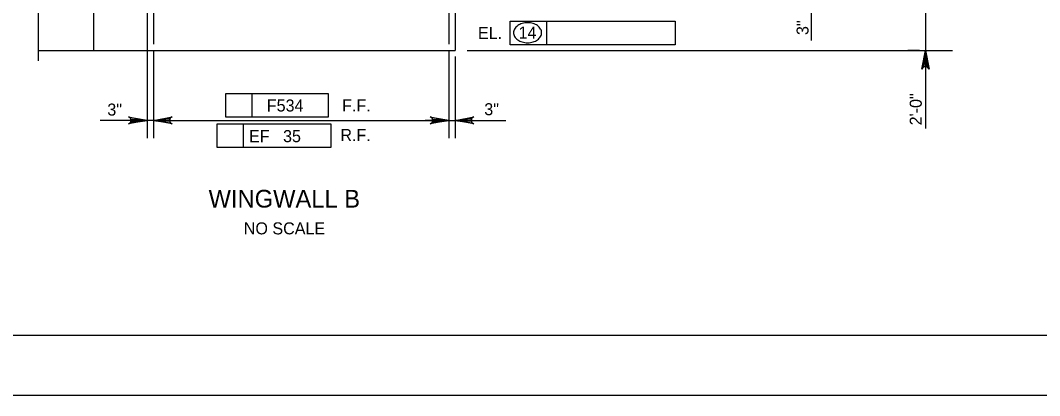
# Model space of a CAD drawing. Extents: x 638255 to 640306, y 296059 to 298435.
# Drawn here: x 638795.2 to 639049.4, y 296059.5 to 296153 of the extents above; entities that cross this region are included whole.
import ezdxf

# ---------------------------------------------------------------- set-up
doc = ezdxf.new("R2010")
doc.units = 0
for name, color, linetype in [('2', 7, 'Continuous'), ('Level 10', 7, 'Continuous'), ('Level 3', 7, 'Continuous'), ('Level 4', 7, 'Continuous'), ('Level 6', 7, 'Continuous'), ('PLT-BNDY', 7, 'Continuous')]:
    doc.layers.add(name, color=color, linetype=linetype)

msp = doc.modelspace()

# ---------------------------------------------------------------- linework, layer by layer
at = {"layer": '2'}
msp.add_line((639261.46, 296074.46), (638475.46, 296074.46), dxfattribs=at)
at = {"layer": 'Level 10'}
for p, q in [((638903.63, 296219.78), (638903.63, 296145.49)), ((638813.44, 296157.77), (638813.44, 296145.49)), ((638799.67, 296145.49), (638903.63, 296145.49))]:
    msp.add_line(p, q, dxfattribs=at)
at = {"layer": 'Level 3'}
msp.add_line((638799.67, 296173.39), (638799.67, 296142.87), dxfattribs=at)
at = {"layer": 'Level 4'}
for p, q in [((638992.48, 296147.95), (638992.48, 296213.97)), ((638826.89, 296156.23), (638826.89, 296123.63)), ((639020.95, 296157.77), (639020.95, 296145.49)), ((638917.35, 296152.73), (638958.48, 296152.73)), ((638917.35, 296146.83), (638917.35, 296152.73)), ((638926.5, 296146.83), (638926.5, 296152.73)), ((638958.48, 296152.73), (638958.48, 296146.83)), ((638828.42, 296145.49), (638828.42, 296123.63)), ((638902.1, 296145.49), (638902.1, 296123.63)), ((638906.62, 296145.49), (638996.24, 296145.49)), ((638958.48, 296146.83), (638917.35, 296146.83)), ((638996.24, 296145.49), (639027.68, 296145.49)), ((639019.48, 296145.49), (639016.53, 296145.49)), ((638903.63, 296143.95), (638903.63, 296123.63)), ((639020.95, 296142.54), (639020.95, 296126.02)), ((638846.5, 296134.75), (638871.98, 296134.75)), ((638846.5, 296128.86), (638846.5, 296134.75)), ((638853.07, 296128.86), (638853.07, 296134.75)), ((638871.98, 296134.75), (638871.98, 296128.86)), ((638820.99, 296128.05), (638815.16, 296128.05)), ((638823.94, 296128.05), (638820.99, 296128.05)), ((638828.42, 296128.05), (638826.89, 296128.05)), ((638831.37, 296128.05), (638899.15, 296128.05)), ((638831.37, 296128.05), (638834.31, 296128.05)), ((638871.98, 296128.86), (638846.5, 296128.86)), ((638899.15, 296128.05), (638896.2, 296128.05)), ((638902.1, 296128.05), (638903.63, 296128.05)), ((638906.58, 296128.05), (638909.53, 296128.05)), ((638909.53, 296128.05), (638916.29, 296128.05)), ((638844.33, 296127.2), (638872.69, 296127.2)), ((638844.33, 296121.31), (638844.33, 296127.2)), ((638850.91, 296121.31), (638850.91, 296127.2)), ((638872.69, 296127.2), (638872.69, 296121.31)), ((638872.69, 296121.31), (638844.33, 296121.31))]:
    msp.add_line(p, q, dxfattribs=at)
for points in [[(639020.95, 296145.49), (639021.82, 296140.84), (639021.57, 296141.2), (639021.26, 296141.38), (639020.95, 296141.43), (639020.63, 296141.38), (639020.32, 296141.2), (639020.07, 296140.84), (639020.95, 296145.49), (639020.32, 296141.2), (639020.63, 296141.38), (639020.95, 296145.49), (639020.95, 296141.43), (639021.26, 296141.38), (639020.95, 296145.49), (639021.57, 296141.2)], [(638826.89, 296128.05), (638822.23, 296127.18), (638822.59, 296127.42), (638822.78, 296127.74), (638822.83, 296128.05), (638822.78, 296128.36), (638822.59, 296128.67), (638822.23, 296128.92), (638826.89, 296128.05), (638822.59, 296128.67), (638822.78, 296128.36), (638826.89, 296128.05), (638822.83, 296128.05), (638822.78, 296127.74), (638826.89, 296128.05), (638822.59, 296127.42)], [(638828.42, 296128.05), (638833.07, 296128.92), (638832.71, 296128.67), (638832.53, 296128.36), (638832.47, 296128.05), (638832.53, 296127.74), (638832.71, 296127.42), (638833.07, 296127.18), (638828.42, 296128.05), (638832.71, 296127.42), (638832.53, 296127.74), (638828.42, 296128.05), (638832.47, 296128.05), (638832.53, 296128.36), (638828.42, 296128.05), (638832.71, 296128.67)], [(638902.1, 296128.05), (638897.45, 296127.18), (638897.8, 296127.42), (638897.99, 296127.74), (638898.04, 296128.05), (638897.99, 296128.36), (638897.8, 296128.67), (638897.45, 296128.92), (638902.1, 296128.05), (638897.8, 296128.67), (638897.99, 296128.36), (638902.1, 296128.05), (638898.04, 296128.05), (638897.99, 296127.74), (638902.1, 296128.05), (638897.8, 296127.42)], [(638903.63, 296128.05), (638908.28, 296128.92), (638907.93, 296128.67), (638907.74, 296128.36), (638907.69, 296128.05), (638907.74, 296127.74), (638907.93, 296127.42), (638908.28, 296127.18), (638903.63, 296128.05), (638907.93, 296127.42), (638907.74, 296127.74), (638903.63, 296128.05), (638907.69, 296128.05), (638907.74, 296128.36), (638903.63, 296128.05), (638907.93, 296128.67)]]:
    msp.add_lwpolyline(points, dxfattribs=at)
for points in [[(639020.46, 296142.54), (639021.44, 296142.54), (639020.95, 296145.49)], [(638823.94, 296128.54), (638823.94, 296127.56), (638826.89, 296128.05)], [(638831.37, 296128.54), (638831.37, 296127.56), (638828.42, 296128.05)], [(638899.15, 296128.54), (638899.15, 296127.56), (638902.1, 296128.05)], [(638906.58, 296128.54), (638906.58, 296127.56), (638903.63, 296128.05)]]:
    msp.add_lwpolyline(points, close=True, dxfattribs=at)
for centre, radius, start, end in [((638920.05, 296149.89), 1.82, 149.9767, 180), ((638920.85, 296149.42), 2.75, 125.6316, 149.9767), ((638921.38, 296148.69), 3.65, 106.5358, 125.6316), ((638921.72, 296147.53), 4.86, 90, 106.5358), ((638921.72, 296147.53), 4.86, 73.4642, 90), ((638922.06, 296148.69), 3.65, 54.3684, 73.4642), ((638922.59, 296149.42), 2.75, 30.0233, 54.3684), ((638923.39, 296149.89), 1.82, 0, 30.0233), ((638920.05, 296149.89), 1.82, 180, 210.0233), ((638920.85, 296150.35), 2.75, 210.0233, 234.3684), ((638921.38, 296151.09), 3.65, 234.3684, 253.4642), ((638922.06, 296151.09), 3.65, 286.5358, 305.6316), ((638922.59, 296150.35), 2.75, 305.6316, 329.9767), ((638923.39, 296149.89), 1.82, 329.9767, 0), ((638921.72, 296152.25), 4.86, 253.4642, 270), ((638921.72, 296152.25), 4.86, 270, 286.5358)]:
    msp.add_arc(centre, radius, start, end, dxfattribs=at)
at = {"layer": 'Level 6'}
for p, q in [((638828.42, 296169.68), (638828.42, 296147.02)), ((638902.1, 296169.68), (638902.1, 296147.02))]:
    msp.add_line(p, q, dxfattribs=at)
at = {"layer": 'PLT-BNDY'}
msp.add_lwpolyline([(638435.46, 296653.46), (639276.46, 296653.46), (639276.46, 296059.46), (638435.46, 296059.46)], close=True, dxfattribs=at)

# ---------------------------------------------------------------- texts
at = {"layer": 'Level 4'}
for s, p in [('3"', (638991.79, 296149.31)), ('2\'-0"', (639020.01, 296126.8))]:
    msp.add_text(s, height=3, rotation=90, dxfattribs=at).set_placement(p)
for s, height, p in [('EL.', 3, (638909.35, 296148.32)), ('14', 3, (638919.48, 296148.43)), ('F534', 3, (638856.69, 296130.25)), ('F.F.', 3, (638875.47, 296130.27)), ('3"', 3, (638816.92, 296129.23)), ('3"', 3, (638910.92, 296129.32)), ('EF   35', 3, (638852.27, 296122.61)), ('R.F.', 3, (638875.03, 296122.89)), ('WINGWALL B', 4.421, (638842.17, 296106.31)), ('NO SCALE', 3, (638850.95, 296099.63))]:
    msp.add_text(s, height=height, dxfattribs=at).set_placement(p)

doc.saveas('drawing.dxf')
